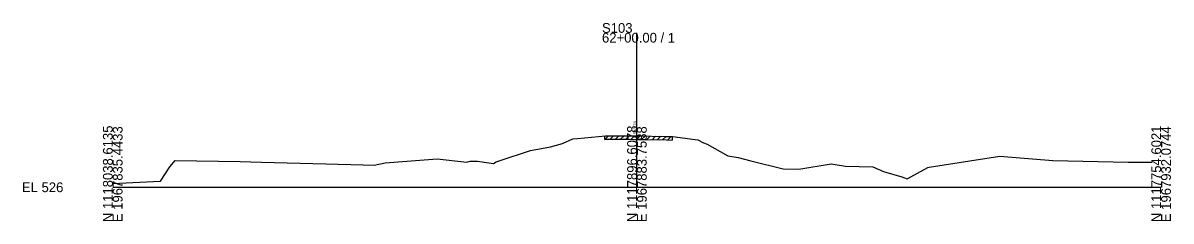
# Model space of a CAD drawing. Extents: x 974 to 1303, y 990 to 14518.
# Drawn here: x 974.3 to 1302.8, y 6490.3 to 6547.1 of the extents above; entities that cross this region are included whole.
import ezdxf

# ---------------------------------------------------------------- set-up
doc = ezdxf.new("R2010")
doc.units = 0
for name, color, linetype in [('Level 10', 7, 'Continuous'), ('Level 60', 7, 'Continuous'), ('Level 61', 7, 'Continuous'), ('Level 63', 7, 'Continuous')]:
    doc.layers.add(name, color=color, linetype=linetype)

msp = doc.modelspace()

# ---------------------------------------------------------------- linework, layer by layer
at = {"layer": 'Level 60'}
for p, q in [((1119.5, 6510.53), (1125.22, 6511.59)), ((1125.22, 6511.59), (1128.66, 6512.59)), ((1128.66, 6512.59), (1131.68, 6513.89)), ((1131.68, 6513.89), (1133.04, 6514.02)), ((1133.04, 6514.02), (1140.99, 6514.76)), ((1140.99, 6514.76), (1147.91, 6514.75)), ((1147.91, 6514.75), (1149.62, 6514.74)), ((1149.62, 6514.74), (1150, 6514.7)), ((1150, 6514.7), (1158.43, 6514.59)), ((1158.43, 6514.59), (1160.21, 6514.54)), ((1160.21, 6514.54), (1166.71, 6513.67)), ((1166.71, 6513.67), (1167.39, 6513.57)), ((1167.39, 6513.57), (1169.02, 6512.75)), ((1169.02, 6512.75), (1170.12, 6512.31)), ((1170.12, 6512.31), (1176.03, 6508.98)), ((1110.84, 6507.67), (1119.5, 6510.53)), ((1176.03, 6508.98), (1179.01, 6508.55)), ((1179.01, 6508.55), (1182.55, 6507.59)), ((1233.62, 6505.77), (1253.85, 6508.92)), ((1253.85, 6508.92), (1269.01, 6507.7)), ((1013.68, 6501.76), (1016.37, 6505.82)), ((1016.37, 6505.82), (1017.85, 6507.72)), ((1017.85, 6507.72), (1036.42, 6507.35)), ((1036.42, 6507.35), (1042.55, 6507.23)), ((1042.55, 6507.23), (1061.01, 6506.75)), ((1061.01, 6506.75), (1071.67, 6506.43)), ((1071.67, 6506.43), (1074.78, 6506.37)), ((1074.78, 6506.37), (1077.94, 6506.98)), ((1077.94, 6506.98), (1092.82, 6508.14)), ((1092.82, 6508.14), (1101.34, 6507.15)), ((1101.34, 6507.15), (1102.26, 6507.52)), ((1102.26, 6507.52), (1104.35, 6507.45)), ((1104.35, 6507.45), (1108.99, 6506.82)), ((1108.99, 6506.82), (1109.76, 6507.31)), ((1109.76, 6507.31), (1110.84, 6507.67)), ((1182.55, 6507.59), (1191.88, 6505.24)), ((1191.88, 6505.24), (1196.32, 6505.15)), ((1196.32, 6505.15), (1205.58, 6506.69)), ((1205.58, 6506.69), (1209.73, 6506.08)), ((1209.73, 6506.08), (1217.46, 6505.9)), ((1217.46, 6505.9), (1220.57, 6504.51)), ((1227.32, 6502.43), (1233.21, 6505.69)), ((1233.21, 6505.69), (1233.62, 6505.77)), ((1269.01, 6507.7), (1290.58, 6507.17)), ((1290.58, 6507.17), (1297.4, 6507.24)), ((1005.72, 6501.38), (1013.68, 6501.76)), ((1220.57, 6504.51), (1225.76, 6502.96)), ((1225.76, 6502.96), (1227.32, 6502.43)), ((1000, 6501.04), (1005.72, 6501.38))]:
    msp.add_line(p, q, dxfattribs=at)
at = {"layer": 'Level 61'}
for p, q in [((1140.83, 6513.74), (1141.84, 6514.76)), ((1140.83, 6513.74), (1140.83, 6514.74)), ((1140.83, 6513.74), (1140.99, 6513.76)), ((1140.99, 6513.76), (1147.91, 6513.75)), ((1142.33, 6513.76), (1143.33, 6514.76)), ((1143.83, 6513.76), (1144.83, 6514.75)), ((1145.33, 6513.75), (1146.33, 6514.75)), ((1146.83, 6513.75), (1147.83, 6514.75)), ((1147.91, 6513.75), (1149.62, 6513.74)), ((1148.33, 6513.75), (1149.32, 6514.74)), ((1149.62, 6513.74), (1150, 6513.7)), ((1149.83, 6513.72), (1150.8, 6514.69)), ((1150, 6513.7), (1158.43, 6513.59)), ((1151.33, 6513.68), (1152.32, 6514.67)), ((1152.83, 6513.66), (1153.82, 6514.65)), ((1154.33, 6513.64), (1155.32, 6514.63)), ((1155.83, 6513.62), (1156.82, 6514.61)), ((1157.33, 6513.6), (1158.32, 6514.59)), ((1158.43, 6513.59), (1160.06, 6513.54)), ((1158.83, 6513.58), (1159.8, 6514.55)), ((1160.06, 6514.54), (1160.06, 6513.54))]:
    msp.add_line(p, q, dxfattribs=at)
at = {"layer": 'Level 63'}
for p, q in [((1150, 6500), (1150, 6544.27)), ((1000, 6500), (1150, 6500)), ((1150, 6500), (1300, 6500))]:
    msp.add_line(p, q, dxfattribs=at)

# ---------------------------------------------------------------- texts
at = {"layer": 'Level 10'}
msp.add_text('540.70', height=0.9, rotation=90, dxfattribs=at).set_placement((1149.95, 6515.2))
at = {"layer": 'Level 63'}
for s, p in [('S103', (1140, 6544.27)), ('62+00.00 / 1', (1140, 6541.47)), ('EL 526', (974, 6498.6))]:
    msp.add_text(s, height=2.8, dxfattribs=at).set_placement(p)
for s, p in [('N 1118038.6135', (1000, 6490)), ('E 1967835.4433', (1002.8, 6490)), ('N 1117896.6078', (1150, 6490)), ('E 1967883.7588', (1152.8, 6490)), ('N 1117754.6021', (1300, 6490)), ('E 1967932.0744', (1302.8, 6490))]:
    msp.add_text(s, height=2.8, rotation=90, dxfattribs=at).set_placement(p)

doc.saveas('drawing.dxf')
